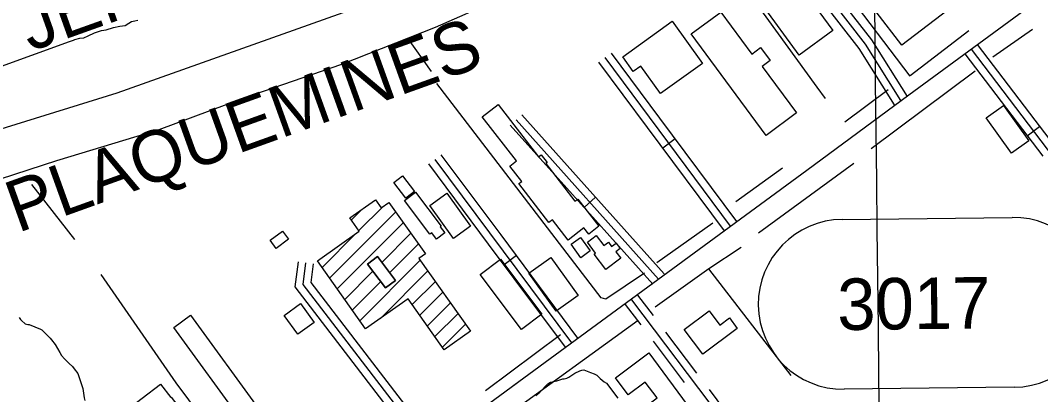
# Model space of a CAD drawing. Extents: x 3683613 to 3738215, y 469626 to 495384.
# Drawn here: x 3691288 to 3693268, y 491540 to 492267 of the extents above; entities that cross this region are included whole.
import ezdxf

# ---------------------------------------------------------------- set-up
doc = ezdxf.new("R2010")
doc.units = 0
for name, color, linetype in [('V-BLDG-OTLN', 7, 'Continuous'), ('V-GRID-MAJR', 7, 'Continuous'), ('V-ROAD-CNTR', 7, 'Continuous'), ('V-ROAD-IDEN', 7, 'Continuous'), ('V-SITE-VEGE', 7, 'Continuous'), ('V-TOPO-BNDY', 7, 'Continuous'), ('V-TOPO-GNAM-IDEN', 7, 'Continuous'), ('V-TOPO-SHOR', 7, 'Continuous')]:
    doc.layers.add(name, color=color, linetype=linetype)

msp = doc.modelspace()

# ---------------------------------------------------------------- linework, layer by layer
at = {"layer": 'V-BLDG-OTLN'}
for p, q in [((3691944.7033353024, 491858.62699850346), (3691991.0861419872, 491905.00980518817)), ((3691887.865180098, 491766.43350424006), (3692016.3735735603, 491894.9418977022)), ((3691930.0321652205, 491879.3111674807), (3691950.1649182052, 491899.4439204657)), ((3691902.537236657, 491745.7502217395), (3692031.0458040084, 491874.25878909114)), ((3691873.19312354, 491787.11678674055), (3691938.8797709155, 491852.80343411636)), ((3691989.1855407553, 491797.0431867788), (3692045.718034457, 491853.57568048)), ((3692004.4083292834, 491776.9106362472), (3692060.390264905, 491832.8925718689)), ((3691946.553406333, 491683.7003742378), (3692063.9375371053, 491801.08450500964)), ((3691917.209293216, 491725.06693923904), (3691972.063729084, 491779.9213751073)), ((3691986.3593621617, 491688.1509910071), (3692078.609441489, 491780.40107033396)), ((3691931.8813497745, 491704.38365673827), (3691987.2867656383, 491759.78907260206)), ((3692048.43673826, 491714.87302804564), (3692093.2813458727, 491759.7176356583)), ((3692063.108761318, 491694.18971204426), (3692107.9532502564, 491739.0342009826)), ((3692077.780784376, 491673.5063960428), (3692122.6251546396, 491718.35076630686)), ((3692092.452807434, 491652.82308004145), (3692137.2970590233, 491697.6673316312)), ((3692107.124830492, 491632.13976404), (3692151.9689634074, 491676.98389695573))]:
    msp.add_line(p, q, dxfattribs=at)
for points in [[(3692865.046, 492247.397), (3692799.69, 492199.335), (3692727.338, 492297.717), (3692744.161, 492310.087), (3692734.586, 492323.104), (3692768.593, 492348.114), (3692779.472, 492333.315), (3692794.003, 492343.999)], [(3693113.251, 492306.466), (3692998.881, 492218.881), (3692949.041, 492283.96), (3693023.977, 492341.349), (3693061.511, 492292.335), (3693100.9450000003, 492322.534)], [(3692735.381, 492043.693), (3692589.87, 492240.74700000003), (3692647.522, 492283.319), (3692707.71, 492201.809), (3692724.4080000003, 492214.14), (3692742.899, 492189.097), (3692727.58, 492177.784), (3692794.41, 492087.283)], [(3692456.8710000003, 492196.31200000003), (3692552.71, 492265.381), (3692611.592, 492183.67600000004), (3692530.501, 492125.234), (3692492.115, 492178.499), (3692477.3680000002, 492167.869)], [(3692350.93, 491840.204), (3692320.458, 491879.669), (3692313.708, 491874.454), (3692255.342, 491950.048), (3692260.7770000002, 491954.249), (3692237.643, 491984.211), (3692250.443, 491994.092), (3692184.2800000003, 492079.783), (3692214.849, 492103.384), (3692293.271, 492001.815), (3692298.524, 492005.873), (3692309.981, 491991.03500000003), (3692307.568, 491989.17100000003), (3692364.156, 491915.881), (3692369.536, 491920.037), (3692410.46, 491867.037), (3692390.93, 491851.957), (3692381.677, 491863.94200000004)], [(3693196.091, 492101.895), (3693245.4760000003, 492033.201), (3693211.752, 492008.957), (3693162.366, 492077.653)], [(3692029.257, 491965.15400000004), (3692052.486, 491934.55100000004), (3692035.628, 491921.757), (3692012.398, 491952.36)], [(3692054.609, 491933.289), (3692104.4760000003, 491867.44), (3692102.5160000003, 491865.957), (3692111.29, 491854.374), (3692095.35, 491842.303), (3692086.093, 491854.525), (3692082.683, 491851.945), (3692033.302, 491917.153)], [(3692082.685, 491907.794), (3692115.5640000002, 491931.27400000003), (3692161.4, 491867.10000000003), (3692128.52, 491843.618)], [(3691864.184, 491799.81700000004), (3691945.502, 491857.501), (3691927.271, 491883.204), (3691976.73, 491918.288), (3691987.802, 491902.68), (3692003.157, 491913.57300000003), (3692073.9420000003, 491813.789), (3692061.292, 491804.814), (3692161.531, 491663.504), (3692110.536, 491627.331), (3692040.267, 491726.39), (3691957.778, 491667.87700000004)], [(3691772.286, 491840.056), (3691796.561, 491857.749), (3691808.171, 491841.822), (3691783.896, 491824.129)], [(3692375.052, 491845.397), (3692393.811, 491819.222), (3692375.345, 491805.98600000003), (3692356.583, 491832.159)], [(3692405.532, 491849.352), (3692420.452, 491829.511), (3692429.17, 491836.071), (3692435.353, 491827.848), (3692444.2800000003, 491834.559), (3692452.063, 491824.211), (3692443.5, 491817.772), (3692453.2260000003, 491804.83900000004), (3692424.1890000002, 491783.005), (3692401.543, 491813.12700000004), (3692404.248, 491815.16500000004), (3692388.29, 491836.386)], [(3691996.592, 491747.483), (3691961.642, 491793.704), (3691980.773, 491808.169), (3692015.722, 491761.94800000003)], [(3691996.592, 491747.483), (3692015.722, 491761.94800000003), (3691980.773, 491808.169), (3691961.642, 491793.704)], [(3692219.785, 491803.37700000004), (3692300.132, 491696.15400000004), (3692260.327, 491666.324), (3692179.98, 491773.547)], [(3692274.554, 491776.09500000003), (3692317.169, 491806.62700000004), (3692370.253, 491732.532), (3692327.6380000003, 491702.001)], [(3691799.654, 491693.827), (3691831.646, 491716.984), (3691858.077, 491680.466), (3691826.085, 491657.309)], [(3691617.714, 491694.253), (3691754.563, 491506.597), (3691722.129, 491482.944), (3691585.281, 491670.603)], [(3692576.276, 491666.36100000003), (3692624.611, 491702.803), (3692645.531, 491675.055), (3692664.072, 491689.03500000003), (3692679.3170000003, 491668.81700000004), (3692612.444, 491618.393)], [(3692442.64, 491572.97000000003), (3692507.651, 491621.139), (3692591.333, 491508.2), (3692527.1890000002, 491460.677), (3692491.073, 491509.42100000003), (3692523.6180000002, 491533.534), (3692500.731, 491564.422), (3692467.318, 491539.664)], [(3691588.949, 491366.462), (3691628.611, 491396.793), (3691620.5130000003, 491407.379), (3691630.77, 491415.221), (3691605.608, 491448.12200000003), (3691559.3310000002, 491412.733), (3691488.182, 491505.76900000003), (3691559.7290000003, 491560.488), (3691579.697, 491534.378), (3691580.602, 491535.07), (3691632.551, 491467.142), (3691630.215, 491465.354), (3691633.608, 491460.916), (3691633.092, 491460.521), (3691664.75, 491419.121), (3691654.596, 491411.353), (3691749.844, 491286.80700000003), (3691686.758, 491238.565)]]:
    msp.add_lwpolyline(points, close=True, dxfattribs=at)
at = {"layer": 'V-GRID-MAJR'}
msp.add_spline([(3693141.066, 475101.816), (3693072.329, 481160.385), (3693003.5700000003, 487220.886), (3692934.811, 493281.396), (3692934.789, 493283.31700000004)], degree=3, dxfattribs=at)
at = {"layer": 'V-ROAD-CNTR'}
for p, q in [((3693242.285476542, 492043.014887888), (3693266.16642878, 492061.1728515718)), ((3692558.919843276, 492036.7099004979), (3692534.8418914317, 492018.812936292)), ((3692404.1541528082, 491923.61512668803), (3692381.790197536, 491903.618166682)), ((3692250.525460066, 491810.30435330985), (3692226.467508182, 491792.38138915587))]:
    msp.add_line(p, q, dxfattribs=at)
for points in [[(3693012.5609359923, 492122.6987285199), (3693890.1881807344, 492767.3854391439), (3694199.0795629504, 492985.8460022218), (3694277.94440522, 493044.8208842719)], [(3692996.989967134, 492111.176751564), (3692927.9571052, 492220.99053193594), (3692802.6533558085, 492383.3022073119)], [(3693009.6889417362, 492119.15973559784), (3692940.2720805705, 492229.58551474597), (3692866.323228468, 492325.37332316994)], [(3692984.290992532, 492103.19376752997), (3692915.6421298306, 492212.3955491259), (3692842.5772759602, 492307.04135983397)], [(3693145.119670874, 492220.3805331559), (3693296.428368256, 492021.37093117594)], [(3692529.0939029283, 492076.8378202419), (3692434.804091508, 492203.69356653)], [(3693121.2377186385, 492202.22256947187), (3693272.5464160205, 492003.2129674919)], [(3693133.1786947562, 492211.3015513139), (3693561.983837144, 491647.313679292)], [(3692505.0159510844, 492058.9418560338), (3692410.726139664, 492185.7976023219)], [(3692666.1886287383, 491867.2462394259), (3692422.7651155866, 492194.7455844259)], [(3692245.4874701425, 491558.36685718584), (3692814.2933325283, 491975.98402195), (3693012.5609359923, 492122.6987285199)], [(3692370.8272194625, 491960.8870521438), (3692260.976439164, 492083.742806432)], [(3692348.46326419, 491940.8910921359), (3692238.612483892, 492063.7468464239)], [(3692526.2809085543, 491764.52544486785), (3692249.794461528, 492073.74482642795)], [(3692678.22760466, 491876.19422153), (3692529.0929029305, 492076.83882024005)], [(3692654.149652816, 491858.2982573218), (3692505.014951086, 492058.9428560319)], [(3692220.65351981, 491850.3992731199), (3692104.672751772, 492006.0719617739)], [(3692196.5955679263, 491832.4753089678), (3692080.6147998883, 491988.147997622)], [(3692357.985245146, 491640.962691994), (3692092.6437758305, 491997.10997969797)], [(3692537.4628861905, 491774.5234248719), (3692370.826219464, 491960.88805214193)], [(3692515.0989309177, 491754.527464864), (3692348.4622641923, 491940.892092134)], [(3692370.0142210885, 491649.9246740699), (3692220.65351981, 491850.40027311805)], [(3692345.956269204, 491632.00070991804), (3692196.5955679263, 491832.47630896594)], [(3692067.729825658, 491427.35111921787), (3691820.8683193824, 491749.54247483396), (3691827.172306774, 491797.8163782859)], [(3692079.636801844, 491436.47410097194), (3691836.5442880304, 491753.7454664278), (3691842.046277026, 491795.8733821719)], [(3692091.5437780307, 491445.597082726), (3691852.2202566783, 491757.9484580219), (3691856.920247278, 491793.9303860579)], [(3692473.910013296, 491724.4935249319), (3692822.2133166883, 491262.82544826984)], [(3692485.8839893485, 491733.5275068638), (3692515.996929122, 491693.61358669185)], [(3692461.936037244, 491715.459543), (3692492.0489770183, 491675.545622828)], [(3692540.0878809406, 491661.68165055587), (3692600.3137604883, 491581.8528102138)], [(3692516.139928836, 491643.613686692), (3692576.365808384, 491563.78484634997)], [(3688672.9996151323, 488939.49109494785), (3688672.9996151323, 488939.49109494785), (3689744.859471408, 489727.799518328), (3690837.197286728, 490528.0509178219), (3691874.7502116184, 491285.8904021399), (3692249.829461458, 491561.5578508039)], [(3692624.404712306, 491549.9208740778), (3692654.518652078, 491510.0069539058)]]:
    msp.add_lwpolyline(points, dxfattribs=at)
at = {"layer": 'V-ROAD-IDEN'}
for p, q in [((3692883.1150325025, 491880.5151327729), (3693213.093681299, 491884.35588004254)), ((3692883.1150325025, 491880.5151327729), (3693213.093681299, 491884.35588004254)), ((3692883.1162143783, 491880.5148904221), (3692883.1150325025, 491880.5151327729)), ((3693216.934428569, 491554.3772312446), (3692886.9557797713, 491550.5364839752)), ((3693216.934428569, 491554.3772312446), (3692886.9557797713, 491550.5364839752))]:
    msp.add_line(p, q, dxfattribs=at)
for centre, radius, start, end in [((3693215.013949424, 491719.3662236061), 165.000000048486, 270.6667571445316, 90.66675714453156), ((3693215.013949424, 491719.3662236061), 165.00000004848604, 270.6667571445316, 90.66675714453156), ((3692885.036293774, 491715.5260627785), 164.99999985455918, 90.66675714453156, 270.6667571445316), ((3692885.036293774, 491715.5260627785), 164.99999985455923, 90.66675714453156, 270.6667571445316)]:
    msp.add_arc(centre, radius, start, end, dxfattribs=at)
at = {"layer": 'V-SITE-VEGE'}
for points in [[(3691284.991, 491689.954), (3691287.977, 491685.733), (3691289.466, 491684.04600000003), (3691296.911, 491677.515), (3691301.787, 491676.476), (3691304.54, 491676.49100000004), (3691326.822, 491667.48600000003), (3691328.946, 491666.01300000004), (3691332.349, 491662.851), (3691334.475, 491660.957), (3691343.204, 491651.677), (3691345.332, 491649.572), (3691348.098, 491646.406), (3691355.131, 491637.331), (3691363.886, 491621.696), (3691367.7260000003, 491615.99700000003)], [(3691367.7260000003, 491615.99700000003), (3691373.051, 491609.667), (3691377.731, 491605.24100000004), (3691382.2, 491600.815), (3691389.005, 491594.493), (3691391.991, 491590.27), (3691398.809, 491581.40400000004), (3691405.035, 491563.855), (3691408.9020000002, 491551.8), (3691411.738, 491534.022), (3691412.397, 491528.73)], [(3692287.946, 491538.093), (3692295.751, 491544.694), (3692311.349, 491561.287), (3692316.841, 491564.066), (3692322.977, 491565.36600000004), (3692328.6890000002, 491566.876), (3692340.322, 491570.52900000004), (3692343.072, 491570.965), (3692348.151, 491572.049), (3692352.589, 491574.18700000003), (3692359.77, 491578.881), (3692364.203, 491581.65400000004), (3692373.9250000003, 491586.358), (3692377.309, 491587.64400000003), (3692381.1180000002, 491588.087), (3692394.483, 491583.28), (3692401.698, 491580.34500000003), (3692406.37, 491578.037), (3692409.984, 491574.87700000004), (3692413.3880000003, 491571.504), (3692420.622, 491564.762), (3692425.293, 491562.24100000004), (3692447.457, 491532.903)]]:
    msp.add_lwpolyline(points, dxfattribs=at)
at = {"layer": 'V-TOPO-BNDY'}
msp.add_lwpolyline([(3693656.843302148, 493291.71905653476), (3692798.101177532, 492671.42973931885), (3692256.1794217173, 492404.1458018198), (3691475.0630859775, 492125.56068865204), (3691044.2578277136, 491992.0943891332), (3690569.2766779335, 491705.80691178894), (3690167.234385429, 491293.53288560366), (3689620.055476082, 490480.6831808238), (3689391.3841074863, 490221.66020227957), (3689222.686803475, 490096.86700584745), (3688304.4662702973, 489656.3013151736), (3687696.061298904, 489259.3810567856)], dxfattribs=at)
at = {"layer": 'V-TOPO-SHOR'}
for p, q in [((3693128.89, 492246.92600000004), (3693014.648, 492159.106)), ((3693252.1920000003, 492249.32), (3693175.6720000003, 492195.794)), ((3692085.528, 492167.593), (3692039.501, 492232.57)), ((3693140.9420000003, 492168.717), (3692939.341, 492017.30700000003)), ((3692972.437, 492132.462), (3692888.344, 492069.166)), ((3692905.4080000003, 491988.958), (3692720.306, 491853.503)), ((3692767.049, 491979.70300000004), (3692676.4420000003, 491914.313)), ((3691393.417, 491841.33400000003), (3691309.8910000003, 491948.543)), ((3692631.863, 491872.972), (3692522.932, 491795.793)), ((3692783.988, 491577.204), (3692623.964, 491784.238)), ((3692487.0530000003, 491684.367), (3692130.94, 491426.221)), ((3692336.162, 491655.939), (3692190.736, 491547.246))]:
    msp.add_line(p, q, dxfattribs=at)
for points in [[(3693014.923, 492158.743), (3692886.316, 492329.072), (3692808.161, 492438.582), (3692757.045, 492512.11600000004)], [(3692616.619, 492437.37200000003), (3692625.2660000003, 492427.126), (3692628.625, 492420.99), (3692631.363, 492415.079), (3692638.33, 492404.25800000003), (3692654.37, 492376.516), (3692661.446, 492369.438), (3692671.02, 492362.286), (3692688.095, 492341.38), (3692716.009, 492299.756), (3692833.609, 492137.457), (3692849.616, 492115.543)], [(3692213.958, 492306.49), (3692092.63, 492253.613), (3691910.813, 492181.601), (3691721.344, 492115.699), (3691556.634, 492054.781), (3691357.8200000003, 491994.34), (3691248.273, 491958.88300000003)], [(3692213.958, 492306.49), (3692092.63, 492253.613), (3691910.813, 492181.601), (3691721.344, 492115.699), (3691556.634, 492054.781), (3691357.8200000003, 491994.34), (3691248.273, 491958.88300000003)], [(3691243.259, 492175.891), (3691383.0270000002, 492225.889), (3691390.64, 492228.892), (3691393.1750000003, 492230.174), (3691403.329, 492232.762), (3691410.739, 492233.43200000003), (3691419.1950000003, 492237.071), (3691431.452, 492242.847), (3691444.774, 492247.356), (3691454.089, 492248.67100000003), (3691468.257, 492253.398), (3691480.5300000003, 492255.784), (3691490.901, 492257.314), (3691497.8710000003, 492261.795), (3691503.363, 492264.78500000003), (3691509.4990000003, 492266.083), (3691515.846, 492267.597)], [(3691243.259, 492175.891), (3691383.0270000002, 492225.889), (3691390.64, 492228.892), (3691393.1750000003, 492230.174), (3691403.329, 492232.762), (3691410.739, 492233.43200000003), (3691419.1950000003, 492237.071), (3691431.452, 492242.847), (3691444.774, 492247.356), (3691454.089, 492248.67100000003), (3691468.257, 492253.398), (3691480.5300000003, 492255.784), (3691490.901, 492257.314), (3691497.8710000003, 492261.795), (3691503.363, 492264.78500000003), (3691509.4990000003, 492266.083), (3691515.846, 492267.597)], [(3692498.878, 491775.983), (3692423.923, 491725.227), (3692415.227, 491727.939), (3692095.801, 492144.553)], [(3692686.673, 491826.042), (3692624.048, 491784.12700000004), (3692519.974, 491709.726)], [(3691989.315, 491409.69800000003), (3691805.255, 491273.713), (3691589.779, 491563.093), (3691444.1410000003, 491773.158)]]:
    msp.add_lwpolyline(points, dxfattribs=at)

# ---------------------------------------------------------------- texts
at = {"layer": 'V-ROAD-IDEN'}
msp.add_text('3017', height=100.00059599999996, rotation=0.6667968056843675, dxfattribs=at).set_placement((3692873.8466820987, 491665.3918308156))
at = {"layer": 'V-TOPO-GNAM-IDEN'}
for s, height, rotation, p in [('JEFFERSON', 99.99980199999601, 19.68228366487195, (3691306.8783473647, 492206.05356181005)), ('PLAQUEMINES', 99.99980199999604, 19.784271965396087, (3691282.501396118, 491853.8422662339))]:
    msp.add_text(s, height=height, rotation=rotation, dxfattribs=at).set_placement(p)

doc.saveas('drawing.dxf')
